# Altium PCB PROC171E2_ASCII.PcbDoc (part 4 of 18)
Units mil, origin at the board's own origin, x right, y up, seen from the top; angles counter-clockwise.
Board outline 7700 x 2300 mil, 6 copper layers (Top Layer, GND 1, SIG 1, SIG 2, GND 2, Bottom Layer), stack 61.062 mil thick; 938 components, 688 nets, 11933 pads, 1723 vias.
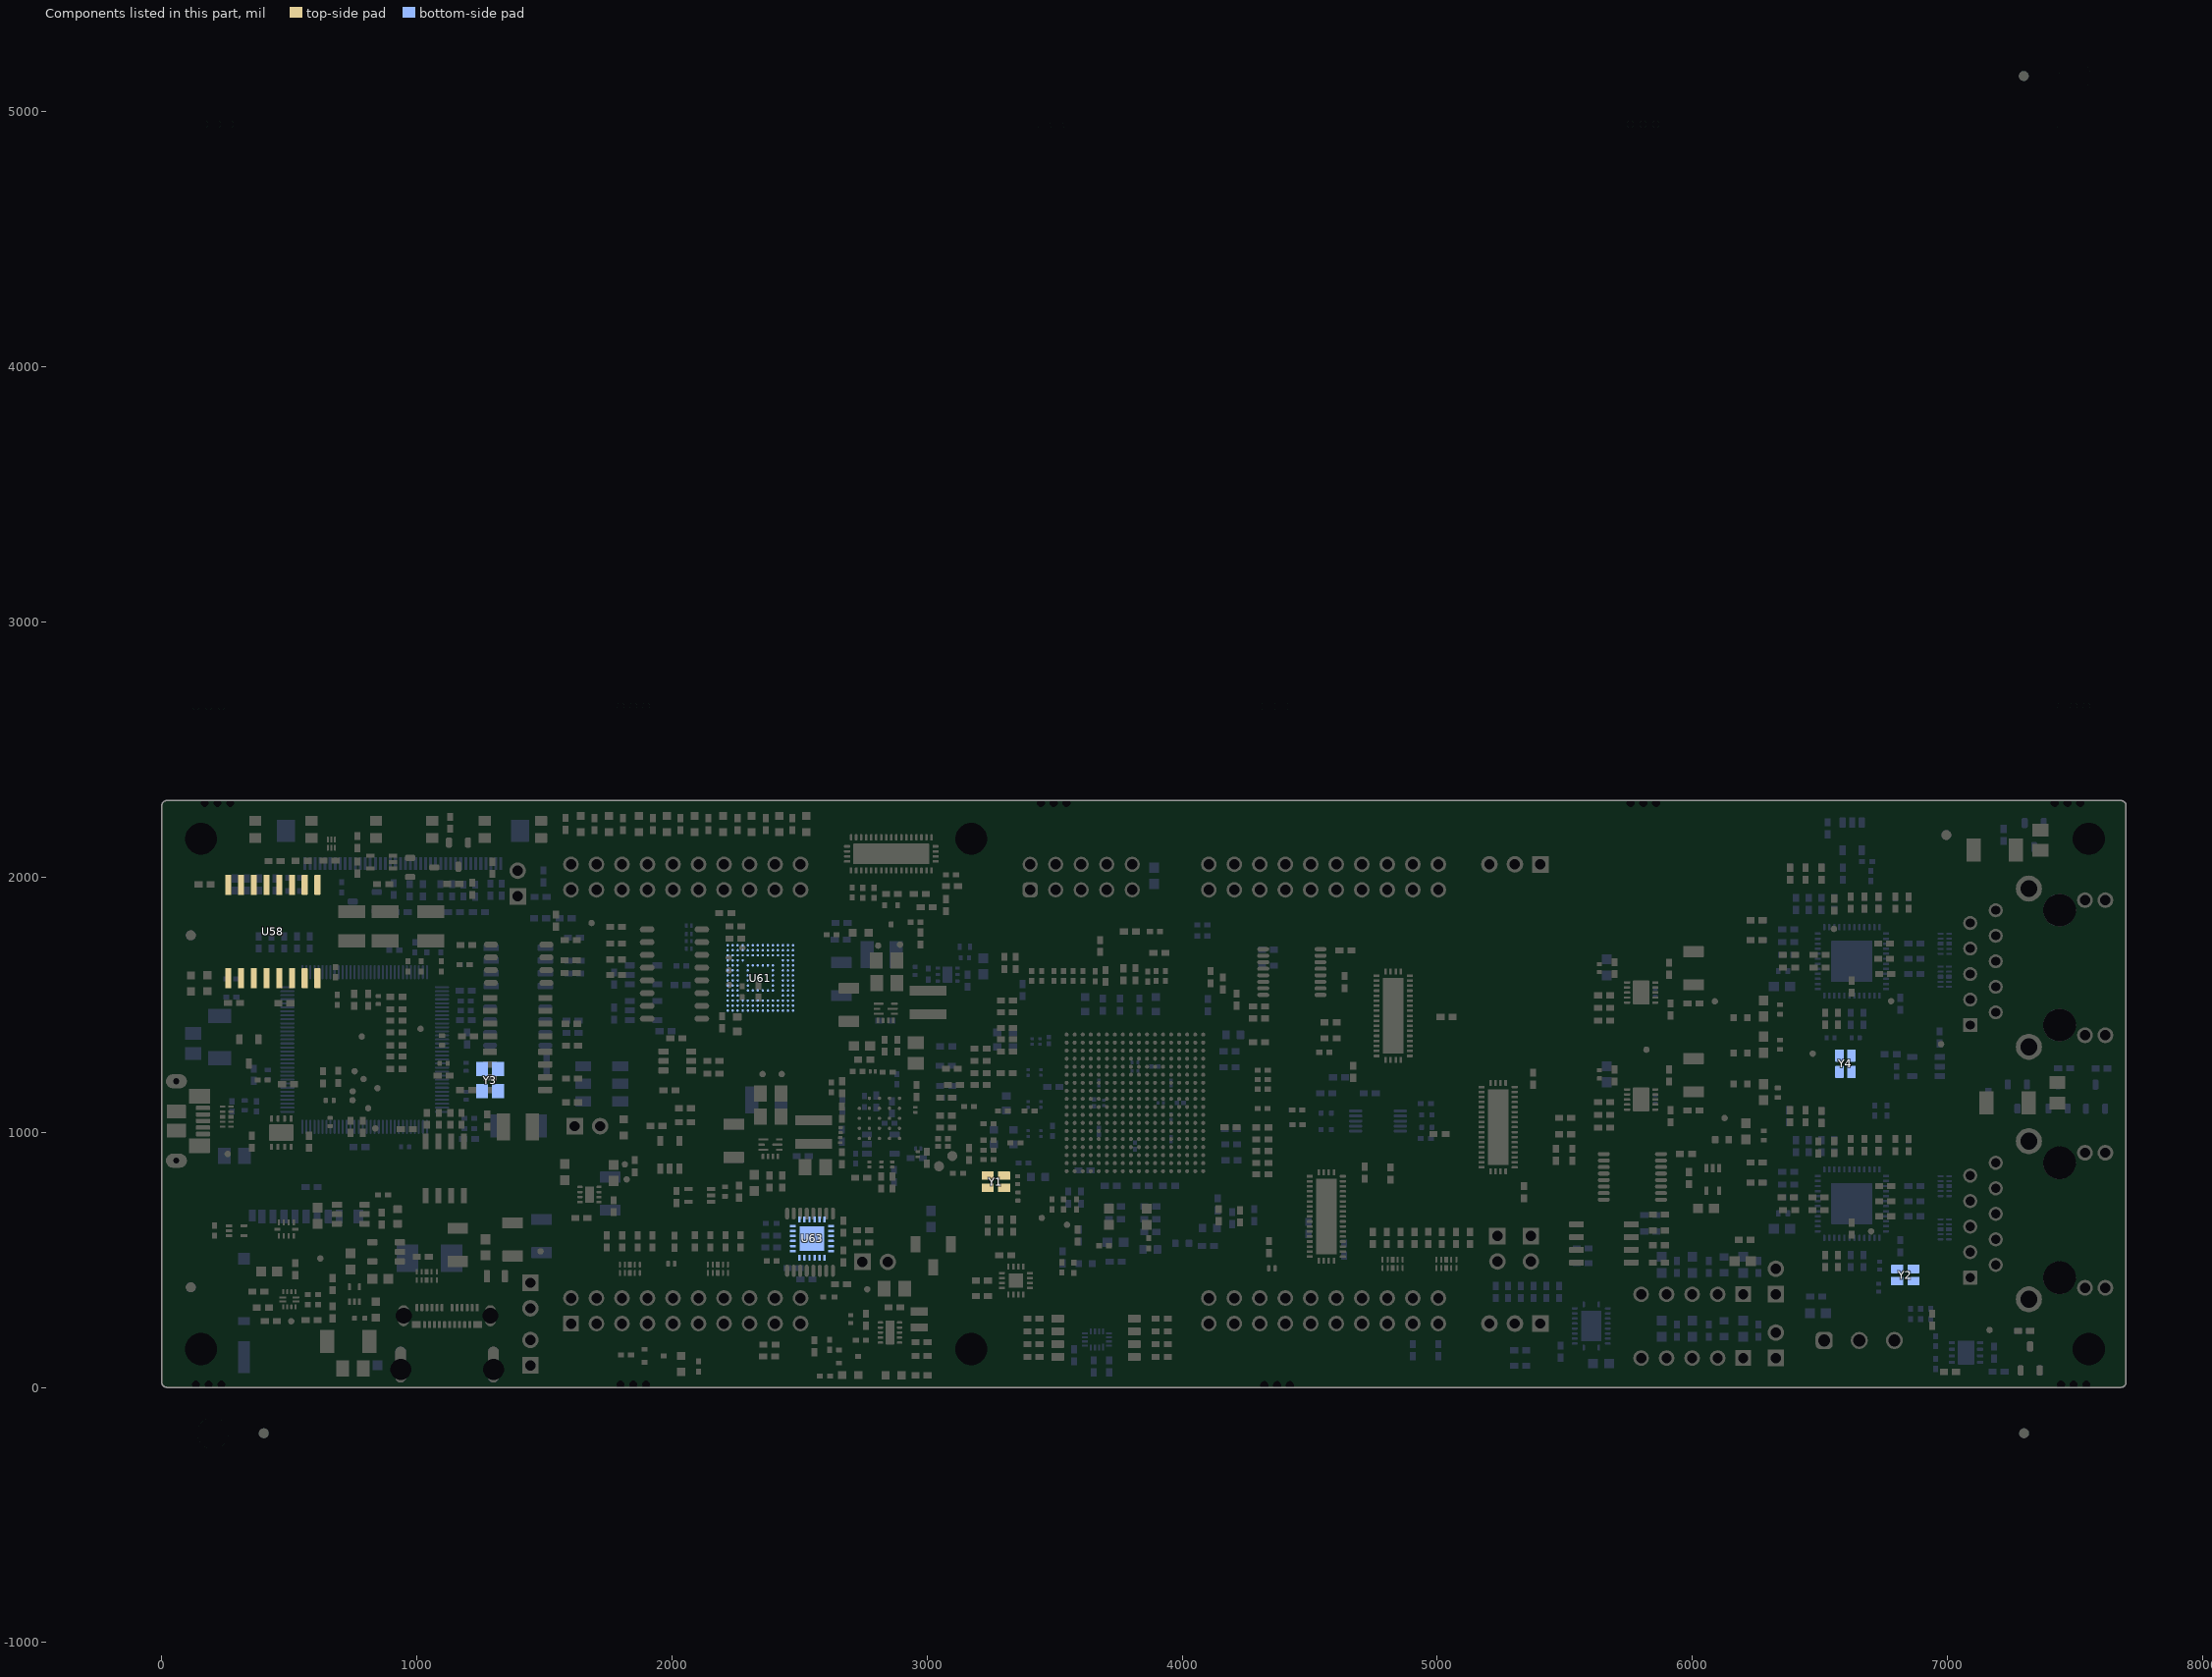
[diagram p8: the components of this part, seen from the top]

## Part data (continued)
U58: library part CMP-0096103-1, "General purpose, 50-Mbps, six-channel (6/0) digital isolator 16-SOIC -40 to 125"
U61: library part CMP-0091989-1, "FLASH - NAND Memory IC 64Gb (8G x 8) MMC 153-TFBGA (11.5x13)"
U63: library part CMP-0043175-2, "Low-Voltage 16-Bit I2C and SMBus I/O Expander, 16 Outputs, 1.65 to 5.5 V, -40 to 85 degC, 24-pin QFN (RTW), Green (RoHS & no Sb/Br)"
Y1 Y2 Y4: library part CMP-0084811-1, "Crystal, 25 MHz, 10 ppm, 4 pF, SMD"
Y3: library part CMP-0004635-3, "Crystal, 16 MHz, 8pF, SMD"
ZZ1: library part CMP-0003616-3
ZZ2: library part CMP-0077236-1
ZZ3: library part CMP-0077237-1
ZZ4: library part CMP-0077238-1

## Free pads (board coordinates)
  round 65.36 on Mech22: 1(-281.58,414) 1(249.42,53) 1(1196.42,275) 1(1203.42,-873) 1(1504.42,253)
